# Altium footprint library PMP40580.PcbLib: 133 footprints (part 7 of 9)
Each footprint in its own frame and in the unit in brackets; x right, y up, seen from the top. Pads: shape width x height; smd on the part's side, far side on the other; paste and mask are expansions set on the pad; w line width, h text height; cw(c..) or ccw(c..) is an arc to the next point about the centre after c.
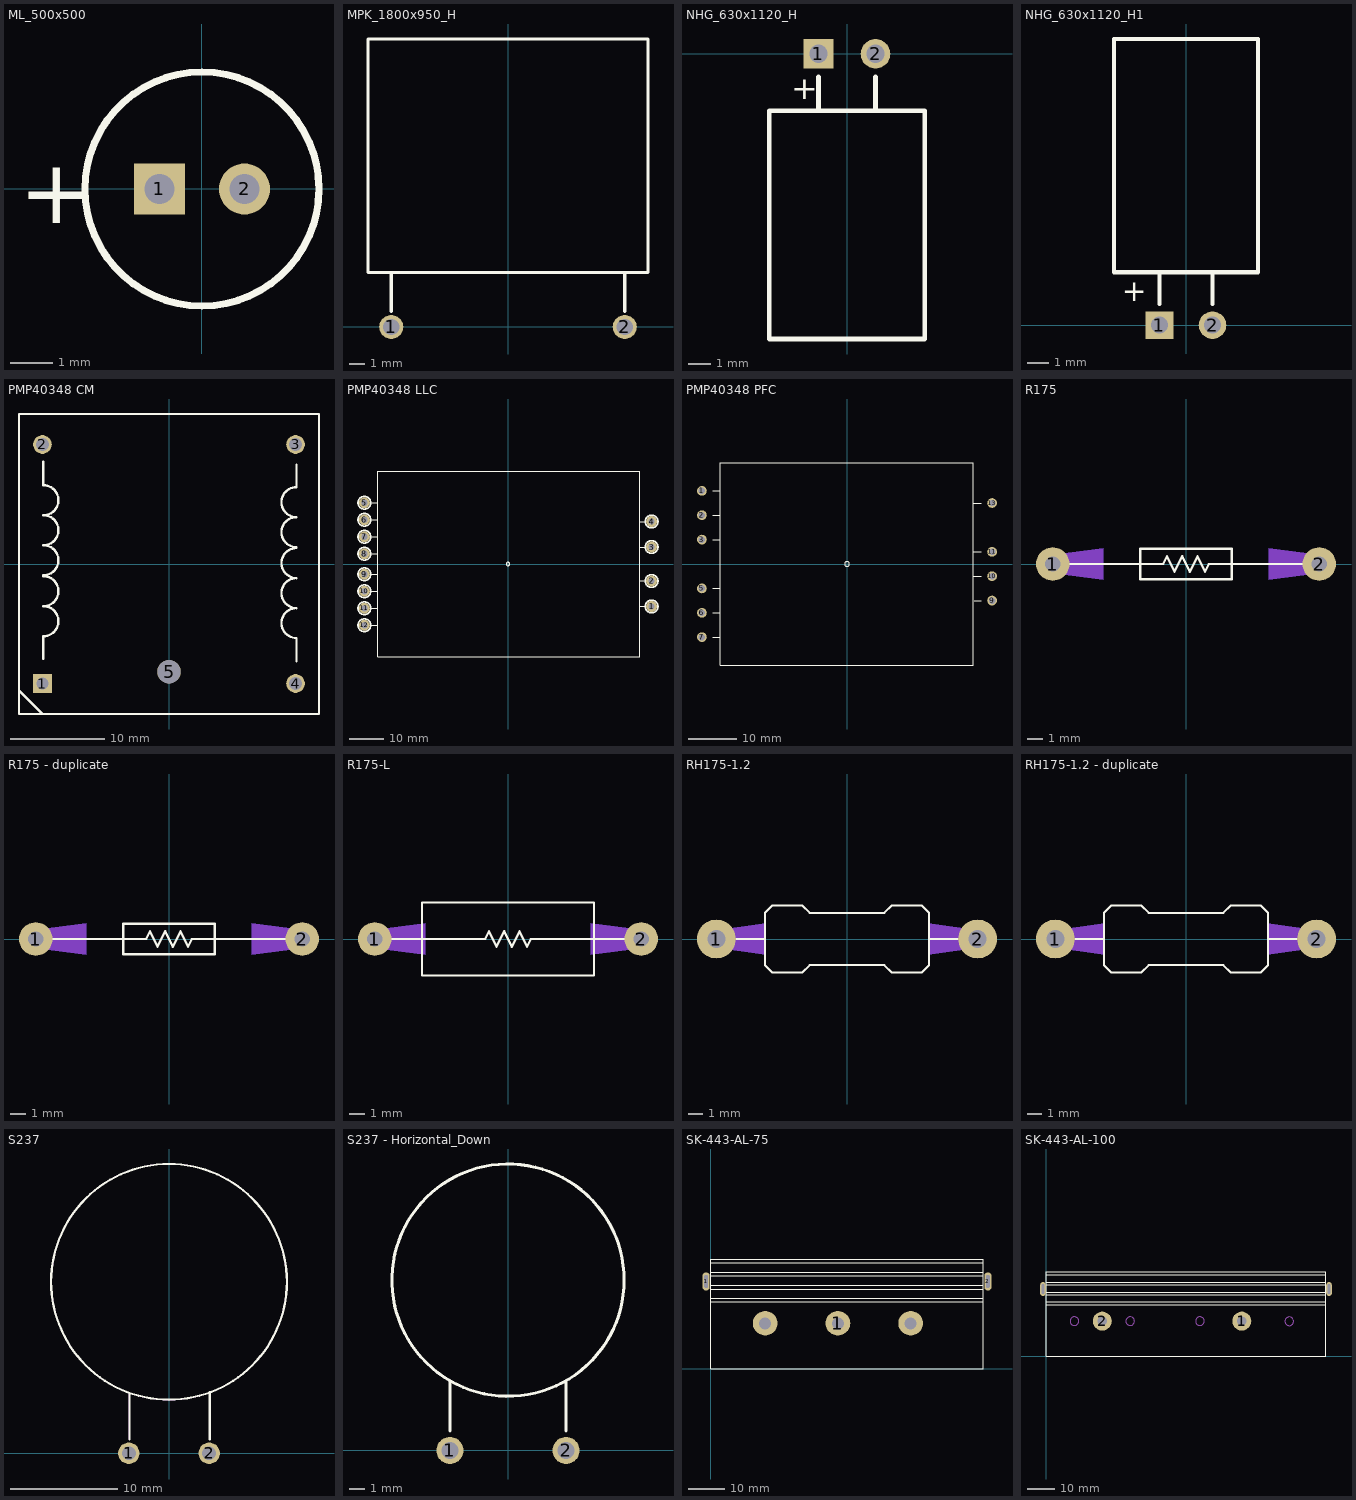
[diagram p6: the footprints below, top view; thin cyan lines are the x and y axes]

## ML_500x500 [mm] "Rubycon"
height 6.5
pads (2):
  rect 1.2x1.2 hole 0.711: 1(-1,0)
  round 1.2 hole 0.711: 2(1,0)
Top Overlay:
  circle w0.17: c0,0 r2.75
  text "+" at -4.3,-0.8 h1.52
Mechanical 5:
  circle w0.1: c0,0 r2.75
  text "+" at -4.3,-0.8 h1.52
  text ".Designator" at -1.9,-0.5 h1.02
3D body "ML_500x500.stp": height 6.51, standoff -4, extent -2.728,-2.745 2.75,2.746

## MPK_1800x950_H [mm] "TH, 2-Leads, Body 18x9.5mm, Lead Spacing 15mm"
height 15
pads (2):
  round 1.55 hole 1.05: 1(-7.5,0) 2(7.5,0)
Top Overlay:
  lines w0.2: -7.5,1 -7.5,3.5 ; 7.5,1 7.5,3.5 ; -9,3.5 -9,18.5 9,18.5 9,3.5 -9,3.5
Mechanical 5:
  lines w0.1: -7.5,1 -7.5,3.5 ; 7.5,1 7.5,3.5 ; -9,3.5 -9,18.5 9,18.5 9,3.5 -9,3.5
  text ".Designator" at -3.1,-0.3 h1.02
3D body: height 0, standoff -2.5, extent 7.103,-0.399 7.9,0.399
3D body: height 0, standoff -2.5, extent -7.897,-0.399 -7.1,0.399

## NHG_630x1120_H [mm] "TH, 2-Leads, Dia 6.3mm, Pin Spacing 2.5mm"
height 12.2
pads (2):
  rect 1.3x1.3 hole 0.8: 1(-1.25,0)
  round 1.3 hole 0.8: 2(1.25,0)
Top Overlay:
  lines w0.2: -1.25,-2.5 -1.25,-1 ; 1.25,-2.5 1.25,-1 ; -3.4,-12.5 -3.4,-2.5 3.4,-2.5 3.4,-12.5 -3.4,-12.5
  text "+" at -2.45,-2 h1.02
Mechanical 5:
  lines w0.15: -1.25,-2.5 -1.25,-1 ; 1.25,-2.5 1.25,-1 ; -3.4,-12.5 3.4,-12.5 3.4,-2.5 -3.4,-2.5 -3.4,-12.5
  text ".Designator" at -1.524,-0.508 h1.02
  text "+" at -2.45,-2 h1.02

## NHG_630x1120_H1 [mm] "TH, 2-Leads, Dia 6.3mm, Pin Spacing 2.5mm"
height 12.2
pads (2):
  rect 1.3x1.3 hole 0.8: 1(-1.25,0)
  round 1.3 hole 0.8: 2(1.25,0)
Top Overlay:
  lines w0.2: -1.25,1 -1.25,2.5 ; 1.25,1 1.25,2.5 ; -3.4,2.5 3.4,2.5 3.4,13.5 -3.4,13.5 -3.4,2.5
  text "+" at -1.85,2 h1.02
Mechanical 5:
  lines w0.15: -1.25,1 -1.25,2.5 ; 1.25,1 1.25,2.5 ; -3.4,2.5 -3.4,13.5 3.4,13.5 3.4,2.5 -3.4,2.5
  text "+" at -1.85,2 h1.02
  text ".Designator" at -1.524,-0.508 h1.02

## PMP40348 CM [mm] "Wurth"
height 35
pads (5):
  rect 2x2 hole 1.3: 1(-13.5,-12.75)
  round 2 hole 1.4: 2(-13.5,12.75) 3(13.5,12.75) 4(13.5,-12.75)
  round 2.5 hole 2.5: 5(0,-11.5)
Top Overlay:
  lines w0.254: -16,-13.5 -13.5,-16 ; -13.4,-10.1 -13.4,-7.703 ccw(c-13.4,-6.1) -13.4,-4.497 ; -13.4,-4.503 ccw(c-13.4,-2.9) -13.4,-1.297 ; -13.4,-1.203 ccw(c-13.4,0.4) -13.4,2.003 ; -13.4,1.997 ccw(c-13.4,3.6) -13.4,5.203 ; -13.4,5.197 ccw(c-13.4,6.8) -13.4,8.403 -13.4,10.9 ; 13.6,-10.4 13.6,-7.903 cw(c13.6,-6.3) 13.6,-4.697 ; 13.6,-4.703 cw(c13.6,-3.1) 13.6,-1.497 ; 13.6,-1.503 cw(c13.6,0.1) 13.6,1.703 ; 13.6,1.797 cw(c13.6,3.4) 13.6,5.003 ; 13.6,4.997 cw(c13.6,6.6) 13.6,8.203 13.6,10.6 ; -16,-16 -16,16 16,16 16,-16 -16,-16

## PMP40348 LLC [mm] "PMP40348 PFC"
pads (12):
  round 3.2 hole 1.8: 1(42.25,-12.5) 2(42.25,-5) 3(42.25,5) 4(42.25,12.5) 5(-42.25,18) 6(-42.25,13) 7(-42.25,8) 8(-42.25,3) 9(-42.25,-3) 10(-42.25,-8) 11(-42.25,-13) 12(-42.25,-18)
Top Overlay:
  circle w0.1: c0,0 r0.5
  circle w0.508: c-42.25,18 r1.875
  circle w0.508: c-42.25,13 r1.875
  circle w0.508: c-42.25,8 r1.875
  circle w0.508: c-42.25,3 r1.875
  circle w0.508: c-42.25,-3 r1.875
  circle w0.508: c-42.25,-8 r1.875
  circle w0.508: c-42.25,-13 r1.875
  circle w0.508: c-42.25,-18 r1.875
  circle w0.508: c42.245,12.497 r1.875
  circle w0.508: c42.245,5.004 r1.875
  circle w0.508: c42.245,-5.004 r1.875
  circle w0.508: c42.245,-12.497 r1.875
  lines w0.1: -41,-18 -38.375,-18 ; -41,-13 -38.375,-13 ; -41,-8 -38.375,-8 ; -41,-3 -38.375,-3 ; -41,3 -38.375,3 ; -41,8 -38.4,8 ; -41,13 -38.375,13 ; -41,18.025 -38.4,18.025 ; 38.75,-5 40.5,-5 ; 38.75,12.5 40.5,12.5 ; 38.8,5 40.5,5 ; 38.85,-12.5 40.5,-12.5 ; -38.375,-27.25 -38.375,27.25 38.75,27.25 38.75,-27.25 -38.375,-27.25

## PMP40348 PFC [mm] "PMP40348 PFC"
pads (10):
  round 2 hole 1.3: 1(-29.75,15) 2(-29.75,10) 3(-29.75,5) 5(-29.75,-5) 6(-29.75,-10) 7(-29.75,-15) 9(29.75,-7.5) 10(29.75,-2.5) 11(29.75,2.5) 13(29.75,12.5)
Top Overlay:
  circle w0.1: c0,0 r0.5
  lines w0.1: -27.5,-15 -26.125,-15 ; -27.5,-10 -26.075,-10 ; -27.5,-5 -26.2,-5 ; -27.5,5 -26.175,5 ; -27.5,10 -26.175,10 ; -27.5,15 -26.2,15 ; 25.925,-2.5 27.5,-2.5 ; 25.925,2.5 27.5,2.5 ; 25.95,12.5 27.5,12.5 ; 26.1,-7.5 27.5,-7.5 ; -25.975,-20.75 -25.975,20.75 25.9,20.75 25.9,-20.75 -25.975,-20.75

## R175 [mm]
pads (2):
  round 2.2 / inner round 1.8 / far side round 2.2 hole 1: 1(-8.75,0) 2(8.75,0)
Bottom Layer:
  region: -7.25,0.45 -8.45,0.95 -8.75,0.95 -8.75,-0.95 -8.45,-0.95 -7.25,-0.45
  region: 7.25,-0.45 8.45,-0.95 8.75,-0.95 8.75,0.95 8.45,0.95 7.25,0.45
  region: -6.95,0 -6.95,0.099 -7.026,0.283 -7.167,0.424 -7.351,0.5 -7.45,0.5 -7.549,0.5 -7.733,0.424 -7.874,0.283 -7.95,0.099 -7.95,0 -7.95,-0.099 -7.874,-0.283 -7.733,-0.424 -7.549,-0.5 -7.45,-0.5 -7.351,-0.5 -7.167,-0.424 -7.026,-0.283 -6.95,-0.099
  region: 7.95,0 7.95,0.099 7.874,0.283 7.733,0.424 7.549,0.5 7.45,0.5 7.351,0.5 7.167,0.424 7.026,0.283 6.95,0.099 6.95,0 6.95,-0.099 7.026,-0.283 7.167,-0.424 7.351,-0.5 7.45,-0.5 7.549,-0.5 7.733,-0.424 7.874,-0.283 7.95,-0.099
Bottom Layer keep-out:
  region: -5.45,-1.05 -5.45,1.05 -8.75,0.6 -8.75,-0.6
  region: -8.75,-0.6 -5.45,-0.6 -5.45,0.6 -8.75,0.612 -8.984,0.565 -9.183,0.433 -9.315,0.234 -9.362,0 -9.315,-0.234 -9.183,-0.433 -8.984,-0.565 -8.75,-0.612
  region: 5.45,1.05 5.45,-1.05 8.75,-0.6 8.75,0.6
  region: 8.75,0.6 5.45,0.6 5.45,-0.6 8.75,-0.612 8.984,-0.565 9.183,-0.433 9.315,-0.234 9.362,0 9.315,0.234 9.183,0.433 8.984,0.565 8.75,0.612
Top Overlay:
  lines w0.15: -8.75,0 -1.5,0 -1.25,0.5 -0.75,-0.5 -0.25,0.5 0.25,-0.5 0.75,0.5 1.25,-0.5 1.5,0 8.75,0 ; -3,-1 3,-1 3,1 -3,1 -3,-1

## R175 - duplicate [mm]
pads (2):
  round 2.2 / inner round 1.8 / far side round 2.2 hole 1: 1(-8.75,0) 2(8.75,0)
Bottom Layer:
  region: -7.25,0.45 -8.45,0.95 -8.75,0.95 -8.75,-0.95 -8.45,-0.95 -7.25,-0.45
  region: 7.25,-0.45 8.45,-0.95 8.75,-0.95 8.75,0.95 8.45,0.95 7.25,0.45
  region: -6.95,0 -6.95,0.099 -7.026,0.283 -7.167,0.424 -7.351,0.5 -7.45,0.5 -7.549,0.5 -7.733,0.424 -7.874,0.283 -7.95,0.099 -7.95,0 -7.95,-0.099 -7.874,-0.283 -7.733,-0.424 -7.549,-0.5 -7.45,-0.5 -7.351,-0.5 -7.167,-0.424 -7.026,-0.283 -6.95,-0.099
  region: 7.95,0 7.95,0.099 7.874,0.283 7.733,0.424 7.549,0.5 7.45,0.5 7.351,0.5 7.167,0.424 7.026,0.283 6.95,0.099 6.95,0 6.95,-0.099 7.026,-0.283 7.167,-0.424 7.351,-0.5 7.45,-0.5 7.549,-0.5 7.733,-0.424 7.874,-0.283 7.95,-0.099
Bottom Layer keep-out:
  region: -5.45,-1.05 -5.45,1.05 -8.75,0.6 -8.75,-0.6
  region: -8.75,-0.6 -5.45,-0.6 -5.45,0.6 -8.75,0.612 -8.984,0.565 -9.183,0.433 -9.315,0.234 -9.362,0 -9.315,-0.234 -9.183,-0.433 -8.984,-0.565 -8.75,-0.612
  region: 5.45,1.05 5.45,-1.05 8.75,-0.6 8.75,0.6
  region: 8.75,0.6 5.45,0.6 5.45,-0.6 8.75,-0.612 8.984,-0.565 9.183,-0.433 9.315,-0.234 9.362,0 9.315,0.234 9.183,0.433 8.984,0.565 8.75,0.612
Top Overlay:
  lines w0.15: -8.75,0 -1.5,0 -1.25,0.5 -0.75,-0.5 -0.25,0.5 0.25,-0.5 0.75,0.5 1.25,-0.5 1.5,0 8.75,0 ; -3,-1 3,-1 3,1 -3,1 -3,-1

## R175-L [mm]
pads (2):
  round 2.2 / inner round 1.8 / far side round 2.2 hole 1: 1(-8.75,0) 2(8.75,0)
Bottom Layer:
  region: -7.25,0.45 -8.45,0.95 -8.75,0.95 -8.75,-0.95 -8.45,-0.95 -7.25,-0.45
  region: 7.25,-0.45 8.45,-0.95 8.75,-0.95 8.75,0.95 8.45,0.95 7.25,0.45
  region: -6.95,0 -6.95,0.099 -7.026,0.283 -7.167,0.424 -7.351,0.5 -7.45,0.5 -7.549,0.5 -7.733,0.424 -7.874,0.283 -7.95,0.099 -7.95,0 -7.95,-0.099 -7.874,-0.283 -7.733,-0.424 -7.549,-0.5 -7.45,-0.5 -7.351,-0.5 -7.167,-0.424 -7.026,-0.283 -6.95,-0.099
  region: 7.95,0 7.95,0.099 7.874,0.283 7.733,0.424 7.549,0.5 7.45,0.5 7.351,0.5 7.167,0.424 7.026,0.283 6.95,0.099 6.95,0 6.95,-0.099 7.026,-0.283 7.167,-0.424 7.351,-0.5 7.45,-0.5 7.549,-0.5 7.733,-0.424 7.874,-0.283 7.95,-0.099
Bottom Layer keep-out:
  region: -5.45,-1.05 -5.45,1.05 -8.75,0.6 -8.75,-0.6
  region: -8.75,-0.6 -5.45,-0.6 -5.45,0.6 -8.75,0.612 -8.984,0.565 -9.183,0.433 -9.315,0.234 -9.362,0 -9.315,-0.234 -9.183,-0.433 -8.984,-0.565 -8.75,-0.612
  region: 5.45,1.05 5.45,-1.05 8.75,-0.6 8.75,0.6
  region: 8.75,0.6 5.45,0.6 5.45,-0.6 8.75,-0.612 8.984,-0.565 9.183,-0.433 9.315,-0.234 9.362,0 9.315,0.234 9.183,0.433 8.984,0.565 8.75,0.612
Top Overlay:
  lines w0.15: -8.75,0 -1.5,0 -1.25,0.5 -0.75,-0.5 -0.25,0.5 0.25,-0.5 0.75,0.5 1.25,-0.5 1.5,0 8.75,0 ; -5.65,-2.4 5.65,-2.4 5.65,2.4 -5.65,2.4 -5.65,-2.4

## RH175-1.2 [mm]
pads (2):
  round 2.6 hole 1.2: 1(-8.75,0) 2(8.75,0)
Bottom Layer:
  region: 7.95,0 7.95,0.099 7.874,0.283 7.733,0.424 7.549,0.5 7.45,0.5 7.351,0.5 7.167,0.424 7.026,0.283 6.95,0.099 6.95,0 6.95,-0.099 7.026,-0.283 7.167,-0.424 7.351,-0.5 7.45,-0.5 7.549,-0.5 7.733,-0.424 7.874,-0.283 7.95,-0.099
  region: -6.95,0 -6.95,0.099 -7.026,0.283 -7.167,0.424 -7.351,0.5 -7.45,0.5 -7.549,0.5 -7.733,0.424 -7.874,0.283 -7.95,0.099 -7.95,0 -7.95,-0.099 -7.874,-0.283 -7.733,-0.424 -7.549,-0.5 -7.45,-0.5 -7.351,-0.5 -7.167,-0.424 -7.026,-0.283 -6.95,-0.099
  region: 7.25,-0.45 8.45,-1.25 8.75,-0.95 8.75,0.95 8.45,1.25 7.25,0.45
  region: -7.25,0.45 -8.45,1.25 -8.75,0.95 -8.75,-0.95 -8.45,-1.25 -7.25,-0.45
Bottom Layer keep-out:
  region: -8.75,-0.6 -5.45,-0.6 -5.45,0.6 -8.75,0.612 -8.984,0.565 -9.183,0.433 -9.315,0.234 -9.362,0 -9.315,-0.234 -9.183,-0.433 -8.984,-0.565 -8.75,-0.612
  region: -5.45,-1.05 -5.45,1.05 -8.75,0.6 -8.75,-0.6
  region: 8.75,0.6 5.45,0.6 5.45,-0.6 8.75,-0.612 8.984,-0.565 9.183,-0.433 9.315,-0.234 9.362,0 9.315,0.234 9.183,0.433 8.984,0.565 8.75,0.612
  region: 5.45,1.05 5.45,-1.05 8.75,-0.6 8.75,0.6
Top Overlay:
  lines w0.15: -7.5,0 -5.5,0 ; 5.5,0 7.5,0 ; -5.5,0 -5.5,-1.75 -5,-2.25 -3,-2.25 -2.5,-1.75 2.5,-1.75 3,-2.25 5,-2.25 5.5,-1.75 5.5,1.75 5,2.25 3,2.25 2.5,1.75 -2.5,1.75 -3,2.25 -5,2.25 -5.5,1.75 -5.5,0

## RH175-1.2 - duplicate [mm]
pads (2):
  round 2.6 hole 1.2: 1(-8.75,0) 2(8.75,0)
Bottom Layer:
  region: -7.25,0.45 -8.45,1.25 -8.75,0.95 -8.75,-0.95 -8.45,-1.25 -7.25,-0.45
  region: 7.25,-0.45 8.45,-1.25 8.75,-0.95 8.75,0.95 8.45,1.25 7.25,0.45
  region: -6.95,0 -6.95,0.099 -7.026,0.283 -7.167,0.424 -7.351,0.5 -7.45,0.5 -7.549,0.5 -7.733,0.424 -7.874,0.283 -7.95,0.099 -7.95,0 -7.95,-0.099 -7.874,-0.283 -7.733,-0.424 -7.549,-0.5 -7.45,-0.5 -7.351,-0.5 -7.167,-0.424 -7.026,-0.283 -6.95,-0.099
  region: 7.95,0 7.95,0.099 7.874,0.283 7.733,0.424 7.549,0.5 7.45,0.5 7.351,0.5 7.167,0.424 7.026,0.283 6.95,0.099 6.95,0 6.95,-0.099 7.026,-0.283 7.167,-0.424 7.351,-0.5 7.45,-0.5 7.549,-0.5 7.733,-0.424 7.874,-0.283 7.95,-0.099
Bottom Layer keep-out:
  region: 5.45,1.05 5.45,-1.05 8.75,-0.6 8.75,0.6
  region: 8.75,0.6 5.45,0.6 5.45,-0.6 8.75,-0.612 8.984,-0.565 9.183,-0.433 9.315,-0.234 9.362,0 9.315,0.234 9.183,0.433 8.984,0.565 8.75,0.612
  region: -5.45,-1.05 -5.45,1.05 -8.75,0.6 -8.75,-0.6
  region: -8.75,-0.6 -5.45,-0.6 -5.45,0.6 -8.75,0.612 -8.984,0.565 -9.183,0.433 -9.315,0.234 -9.362,0 -9.315,-0.234 -9.183,-0.433 -8.984,-0.565 -8.75,-0.612
Top Overlay:
  lines w0.15: -7.5,0 -5.5,0 ; 5.5,0 7.5,0 ; -5.5,0 -5.5,1.75 -5,2.25 -3,2.25 -2.5,1.75 2.5,1.75 3,2.25 5,2.25 5.5,1.75 5.5,-1.75 5,-2.25 3,-2.25 2.5,-1.75 -2.5,-1.75 -3,-2.25 -5,-2.25 -5.5,-1.75 -5.5,0

## S237 [mm] "EPCOS"
height 22
pads (2):
  round 2 hole 1.3: 1(-3.75,0) 2(3.75,0)
Top Overlay:
  circle w0.2: c0,16 r11
  lines w0.2: -3.7,1.3 -3.7,5.6 ; 3.8,1.3 3.8,5.7
Mechanical 5:
  circle w0.1: c0,16 r11
  lines w0.1: -3.7,1.3 -3.7,5.6 ; 3.8,1.3 3.8,5.7
  text ".Designator" at -1.9,-0.6 h1.02

## S237 - Horizontal_Down [mm] "EPCOS"
height 22
pads (2):
  round 1.75 hole 1.1: 1(-3.75,0) 2(3.75,0)
Top Overlay:
  circle w0.2: c0,11 r7.5
  lines w0.2: -3.75,1.25 -3.75,4.5 ; 3.75,1.25 3.75,4.5
Mechanical 5:
  text ".Designator" at -4.75,10.5 h1.02
3D body: height 3.42, standoff 2.58, extent 3.328,0.076 4.175,5.076
3D body: height 3.42, standoff 2.58, extent -4.173,0.076 -3.327,5.076
3D body: height 3, standoff -4, extent 3.328,-0.424 4.175,0.424
3D body: height 3, standoff -4, extent -4.172,-0.424 -3.325,0.424
3D body: height 7, standoff 0, extent -7.5,3.5 7.5,18.5
3D body: height 3.42, standoff 2.57, extent -4.175,-0.422 -3.326,0.422
3D body: height 3.42, standoff 2.57, extent 3.325,-0.422 4.174,0.422

## SK-443-AL-75 [mm]
height 12.5
pads (5):
  oval 2x5 hole 1 slot 3.5 at 90 deg: 1(-1.25,24) 2(76.25,24)
  round 6.8 hole 3.3: 1(35,12.5) ""(15,12.5) ""(55,12.5)
Top Overlay:
  lines w0.2: 0,18.4 75,18.4 ; 0,19.4 75,19.4 ; 0,21.9 75,21.9 ; 0,22.9 75,22.9 ; 0,25.5 75,25.5 ; 0,26.5 75,26.5 ; 0,29.1 75,29.1 ; 0,0 75,0 75,30.1 0,30.1 0,0
3D body "sk443.stp": height 12.45, standoff -0.05, extent 65,0 75,30.1
3D body "sk443.stp": height 12.45, standoff -0.05, extent 60,0 70,30.1
3D body "sk443.stp": height 12.45, standoff -0.05, extent 50,0 60,30.1
3D body "sk443.stp": height 12.45, standoff -0.05, extent 40,0 50,30.1
3D body "sk443.stp": height 12.45, standoff -0.05, extent 30,0 40,30.1
3D body "sk443.stp": height 12.45, standoff -0.05, extent 20,0 30,30.1
3D body "sk443.stp": height 12.45, standoff -0.05, extent 10,0 20,30.1
3D body "sk443.stp": height 12.45, standoff -0.05, extent 0,0 10,30.1

## SK-443-AL-100 [mm]
height 12.5
pads (4):
  round 6.8 hole 3.3: 1(70,12.5) 2(20,12.5)
  oval 2x5 hole 1 slot 3.5 at 90 deg: ""(-1.25,24) ""(101.25,24)
Top Overlay:
  lines w0.2: 0,18.4 100,18.4 ; 0,19.4 100,19.4 ; 0,21.9 100,21.9 ; 0,22.9 100,22.9 ; 0,25.5 100,25.5 ; 0,26.5 100,26.5 ; 0,29.1 100,29.1 ; 0,0 100,0 100,30.1 0,30.1 0,0
Mechanical 5:
  circle w0.1: c10,12.5 r1.55
  circle w0.1: c20,12.5 r1.55
  circle w0.1: c30,12.5 r1.55
  circle w0.1: c55,12.5 r1.55
  circle w0.1: c87,12.448 r1.55
  circle w0.1: c70,12.5 r1.55
3D body "sk443.stp": height 12.45, standoff -0.05, extent 90,0 100,30.1
3D body "sk443.stp": height 12.45, standoff -0.05, extent 80,0 90,30.1
3D body "sk443.stp": height 12.45, standoff -0.05, extent 70,0 80,30.1
3D body "sk443.stp": height 12.45, standoff -0.05, extent 60,0 70,30.1
3D body "sk443.stp": height 12.45, standoff -0.05, extent 50,0 60,30.1
3D body "sk443.stp": height 12.45, standoff -0.05, extent 40,0 50,30.1
3D body "sk443.stp": height 12.45, standoff -0.05, extent 30,0 40,30.1
3D body "sk443.stp": height 12.45, standoff -0.05, extent 20,0 30,30.1
3D body "sk443.stp": height 12.45, standoff -0.05, extent 10,0 20,30.1
3D body "sk443.stp": height 12.45, standoff -0.05, extent 0,0 10,30.1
